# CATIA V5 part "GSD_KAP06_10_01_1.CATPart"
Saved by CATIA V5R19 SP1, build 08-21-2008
Part number: GSD_LOFT_01
Definition: Beispielmodell für die Funktion Fläche mit Mehrfachschnitten / Multi-sections surface.
Description: CATIA V5 Flächenmodellierung  Copyright (c) 2009 Maik Hertha IT Consultants
Bounding box of the stored display mesh (mm): x 10 to 220.867, y -27.627 to 70.001, z -5.054 to 20.81
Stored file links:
  \GSD_BUCH_UEBUNG\GSD_KAP06_10_01_1.CATPart
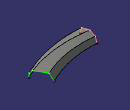
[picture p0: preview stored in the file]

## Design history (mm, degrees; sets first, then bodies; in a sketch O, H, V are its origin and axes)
AxisSystem1 "Absolute Axis System": origin (0, 0, 0), X (1, 0, 0), Y (0, 1, 0), Z (0, 0, 1)
Set1 "Loft 4"
  Plane1: type Equation, A 1, B 0, C 0, RefAxis AxisSystem1, Length 10
  Sketch1 on Plane1, origin (10, 0, 0), H (0, 1, 0), V (0, 0, 1)
    line L1 (-27.0396, -4.8684) -> (-22.2875, 14.1604)
    line L2 (-22.2875, 14.1604) -> (-7.9956, 17.2176)
    line L3 (-7.9956, 17.2176) -> (4.236, 19.8342)
    line L4 (4.236, 19.8342) -> (21.6606, 11.5532)
    line L5 (21.6606, 11.5532) -> (27.3129, -5.0544)
    curve C1
    parallelism: L3 L2
  Plane2: type Equation, A 0, B 0, C 1, RefAxis AxisSystem1, Length 10
  Sketch2 on Plane2, origin (0, 0, 10), H (1, 0, 0), V (0, 1, 0)
    spline S1 through (-9.3532, 23.8094) (121.5676, 21.2269) (200.6804, 53.0779)
    curve C1
  Plane3: type Normal, Curve Sketch2.C1, RefPoint {point type OnCurve, Support Sketch2.C1, Ratio 1}
  Sketch3 on Plane3, origin (200.6804, 53.0779, 10), H (-0.5068, 0.8621, 0), V (0, 0, 1)
    line L1 (-39.835, -9.7536) -> (-39.835, 2.9586)
    line L2 (-39.835, 2.9586) -> (-31.208, 10.8099)
    line L3 (-31.208, 10.8099) -> (7.2722, 10.8099)
    line L4 (7.2722, 10.8099) -> (19.6305, -9.7536)
    curve C1
    vertical: L1 V
    horizontal: L3 H
  Loft1: Sections (Sketch3.C1; Sketch1.C1), SectionCouplingPoints ({coupling CouplingPoints ({point type OnCurve, Support Sketch3.C1, Ratio 0.853628}; {point type OnCurve, Support Sketch1.C1, Ratio 0.765314})}; {coupling CouplingPoints ({point type OnCurve, Support Sketch3.C1, Ratio 0.719316}; {point type OnCurve, Support Sketch1.C1, Ratio 0.440761})}; {coupling CouplingPoints ({point type OnCurve, Support Sketch3.C1, Ratio 0.276243}; {point type OnCurve, Support Sketch1.C1, Ratio 0.209915})})
Body1 (main body)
